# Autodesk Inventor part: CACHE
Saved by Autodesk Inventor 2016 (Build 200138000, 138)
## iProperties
Created: 2013-10
Part Number: CACHE
Material: Générique
Document SubType Name: Modeling
Designer: Bruno
Density: 1 g/cm^3
Appearance: Par défaut
Author: Bruno
Sending System: SolidWorks 2013
Last Author: christophe
Last Saved: 2014-02-15
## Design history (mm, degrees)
feature "Congé1"
feature "Congé2"
node "Solide1"
node "Solide2"
